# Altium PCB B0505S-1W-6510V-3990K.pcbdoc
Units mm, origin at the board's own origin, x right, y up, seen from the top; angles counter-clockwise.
Board outline 11.8 x 10.32 mm, 2 copper layers (Top Layer, Bottom Layer), stack 0.78 mm thick; 9 components, 9 nets, 28 pads, 12 vias.
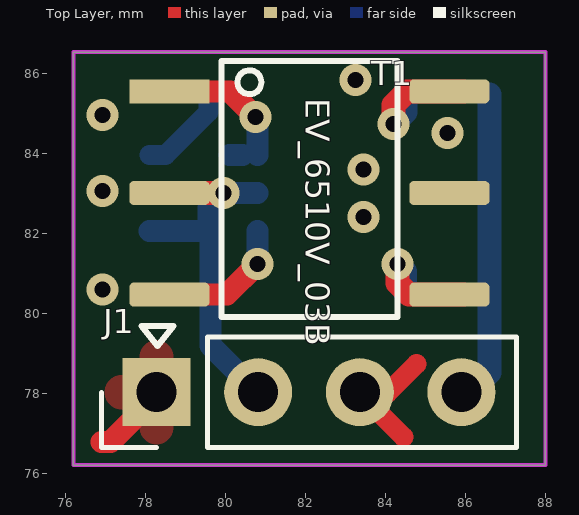
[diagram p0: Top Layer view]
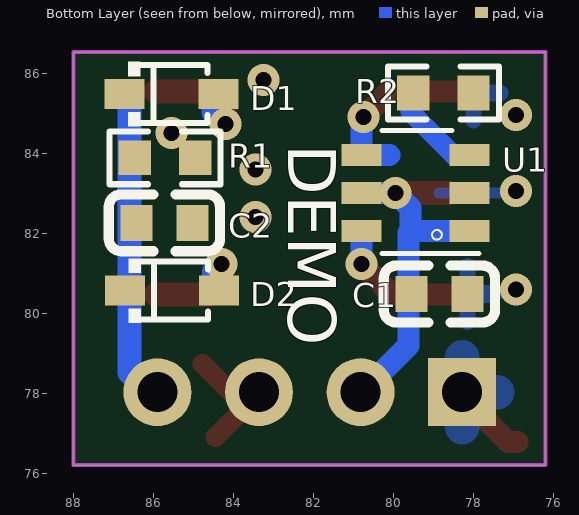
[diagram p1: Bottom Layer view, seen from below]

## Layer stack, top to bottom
Top Solder Mask Layer: solder mask 0.01, Dk 3.3
Top Layer: signal copper 0.035
Dielectric1: surface 0.71, FR4, Dk 4.5
Bottom Layer: signal copper 0.035
Bottom Solder Mask Layer: solder mask 0.01, Dk 3.3

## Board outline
76.2,86.52 88,86.52 88,76.2 76.2,76.2

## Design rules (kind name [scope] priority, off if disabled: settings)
BoardOutlineClearance safeClearance [All] p0: genericclearance=0.254 ignorepadtopadclearanceinfootprint=FALSE except(0: Arc-SplitContinuation Track-SplitContinuation SMDPad-SplitContinuation THPad-SplitContinuation Via-SplitContinuation Fill-SplitContinuation Poly-SplitContinuation Region-SplitContinuation Text-SplitContinuation)
BoardOutlineClearance Plane_innerPlane [All] p0: genericclearance=0.254 ignorepadtopadclearanceinfootprint=FALSE except(0: Arc-SplitContinuation Track-SplitContinuation SMDPad-SplitContinuation THPad-SplitContinuation Via-SplitContinuation Fill-SplitContinuation Poly-SplitContinuation Region-SplitContinuation Text-SplitContinuation)
BoardOutlineClearance Copper_CopperRegion [All] p0: genericclearance=0.254 ignorepadtopadclearanceinfootprint=FALSE except(0: Arc-SplitContinuation Track-SplitContinuation SMDPad-SplitContinuation THPad-SplitContinuation Via-SplitContinuation Fill-SplitContinuation Poly-SplitContinuation Region-SplitContinuation Text-SplitContinuation)
BoardOutlineClearance Copper_CopperRegion1 [All] p0: genericclearance=0.254 ignorepadtopadclearanceinfootprint=FALSE except(0: Arc-SplitContinuation Track-SplitContinuation SMDPad-SplitContinuation THPad-SplitContinuation Via-SplitContinuation Fill-SplitContinuation Poly-SplitContinuation Region-SplitContinuation Text-SplitContinuation)
BoardOutlineClearance Copper_CopperRegion2 [All] p0: genericclearance=0.254 ignorepadtopadclearanceinfootprint=FALSE except(0: Arc-SplitContinuation Track-SplitContinuation SMDPad-SplitContinuation THPad-SplitContinuation Via-SplitContinuation Fill-SplitContinuation Poly-SplitContinuation Region-SplitContinuation Text-SplitContinuation)
BoardOutlineClearance Copper_CopperRegion3 [All] p0: genericclearance=0.254 ignorepadtopadclearanceinfootprint=FALSE except(0: Arc-SplitContinuation Track-SplitContinuation SMDPad-SplitContinuation THPad-SplitContinuation Via-SplitContinuation Fill-SplitContinuation Poly-SplitContinuation Region-SplitContinuation Text-SplitContinuation)
BoardOutlineClearance otherClearance [All] p0: genericclearance=0.254 ignorepadtopadclearanceinfootprint=FALSE except(0: Arc-SplitContinuation Track-SplitContinuation SMDPad-SplitContinuation THPad-SplitContinuation Via-SplitContinuation Fill-SplitContinuation Poly-SplitContinuation Region-SplitContinuation Text-SplitContinuation)
Clearance safeClearance [All] p1: gap=0.178 ignorepadtopadclearanceinfootprint=FALSE
Clearance Plane_innerPlane [All] p1: gap=0.178 ignorepadtopadclearanceinfootprint=FALSE
Clearance Copper_CopperRegion [All] p1: gap=0.178 ignorepadtopadclearanceinfootprint=FALSE
Clearance Copper_CopperRegion1 [All] p1: gap=0.178 ignorepadtopadclearanceinfootprint=FALSE
Clearance Copper_CopperRegion2 [All] p1: gap=0.178 ignorepadtopadclearanceinfootprint=FALSE
Clearance Copper_CopperRegion3 [All] p1: gap=0.178 ignorepadtopadclearanceinfootprint=FALSE
Clearance otherClearance [All] p1: gap=0.178 ignorepadtopadclearanceinfootprint=FALSE
DiffPairsRouting differentialPair [All] p1: maxuncoupledlength=10 minlimit=6 maxlimit=Infinity mostfreqgap=6 toplayer_minwidth=5 toplayer_prefwidth=10 toplayer_maxwidth=100 bottomlayer_minwidth=5 bottomlayer_prefwidth=10 bottomlayer_maxwidth=100
PasteMaskExpansion Common [All] p1: expansion=0
PlaneConnect innerPlane [All] p1: planeconnectstyle=Relief reliefexpansion=0.508 reliefentries=4 reliefconductorwidth=0.254 reliefairgap=0.254
PolygonConnect CopperRegion [All] p1: connectstyle=Relief reliefentries=4 reliefconductorwidth=0 polygonreliefangle="90 Angle" airgapwidth=1
PolygonConnect CopperRegion1 [All] p1: connectstyle=Relief reliefentries=4 reliefconductorwidth=19.685 polygonreliefangle="90 Angle" airgapwidth=19.685
PolygonConnect CopperRegion2 [All] p1: connectstyle=Direct reliefentries=4 reliefconductorwidth=10 polygonreliefangle="90 Angle" airgapwidth=10
PolygonConnect CopperRegion3 [All] p1: connectstyle=Relief reliefentries=4 reliefconductorwidth=0 polygonreliefangle="90 Angle" airgapwidth=1
RoutingVias viaSize [All] p1: viastyle="Through Hole" holewidth=12 minholewidth=11.8 maxholewidth=236.2 width=12 minwidth=11.8 maxwidth=236.2
SolderMaskExpansion Common [All] p1: useseparateexpansions=TRUE expansion=0 expansionbottom=0
Width trackWidth [All] p1: maxlimit=100 minlimit=5 preferedwidth=10

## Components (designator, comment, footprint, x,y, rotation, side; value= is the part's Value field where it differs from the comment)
C1 "" C0603 78.85,80.475 r0 bottom
C2 "" C0603 85.725,82.254 r0 bottom
D1 "" SOD-323_L1.8-W1.3-LS2.5-RD 85.55,85.474 r180 bottom
D2 "" SOD-323_L1.8-W1.3-LS2.5-RD 85.538,80.56 r180 bottom
J1 "Connector_Generic_Conn_01x04" coileasy:PinHeader_01x04_P2.54mm_Vertical 78.27,78 r90 top
R1 "" R0603 85.71,83.88 r180 bottom
R2 "" R0603 78.75,85.5 r180 bottom
T1 "CMT3990K" coileasy:CMT38xxx 82.1,83 r0 top
U1 "" SOT-23-6_L2.9-W1.6-P0.95-LS2.8-BR 79.292,82.971 r0 bottom

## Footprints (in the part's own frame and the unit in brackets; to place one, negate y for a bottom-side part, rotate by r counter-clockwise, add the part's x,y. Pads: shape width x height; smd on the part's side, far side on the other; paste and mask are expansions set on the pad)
C0603 [mm]
  rect 0.8x0.9 smd: 1(-0.7,0) 2(0.7,0)
  silkscreen extent -1.39,-0.71 1.39,0.71
coileasy:CMT38xxx [mm]
  rect 2x0.6 smd: 1(-3.5,2.54)
  rrect37% 2x0.6 smd: 2(-3.5,0) 3(-3.5,-2.54) 4(3.5,-2.54) 5(3.5,0) 6(3.5,2.54)
  silkscreen extent -2.2,-3.1 2.2,3.3
coileasy:PinHeader_01x04_P2.54mm_Vertical [mm]
  rect 1.7x1.7 hole 1: 1(0.02,-0.01)
  round 1.7 hole 1: 2(0.02,-2.55) 3(0.02,-5.09) 4(0.02,-7.63)
  silkscreen extent -1.36,-9.01 1.4,1.37
R0603 [mm]
  rect 0.806x0.864 smd: 1(-0.753,0) 2(0.753,0)
  silkscreen extent -1.39,-0.66 1.39,0.66
SOD-323_L1.8-W1.3-LS2.5-RD [mm]
  rect 1x0.75 smd: 1(-1.173,0) 2(1.173,0)
  silkscreen extent -1.08,-0.8 0.9,0.8
SOT-23-6_L2.9-W1.6-P0.95-LS2.8-BR [mm]
  rect 1x0.55 smd: 1(-1.192,0.921) 2(-1.192,-0.029) 3(-1.192,-0.979) 4(1.508,-0.979) 5(1.508,-0.029) 6(1.508,0.921)
  silkscreen extent -1.43,-1.59 1,1.48

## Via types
v1: diameter 0.8, hole 0.4, Top Layer to Bottom Layer, 12 vias

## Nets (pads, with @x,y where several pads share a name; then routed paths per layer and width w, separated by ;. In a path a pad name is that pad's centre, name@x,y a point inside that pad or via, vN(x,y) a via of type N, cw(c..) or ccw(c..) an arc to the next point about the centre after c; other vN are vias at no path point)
0V: C2.1 J1.3 R1.2 T1.5 | length 3.3
  Top Layer w0.5: 84.45,76.9 83.35,78 84.05,78 84.775,78.725
  other v1: 83.45,82.4 83.45,83.585 85.55,84.5 83.253,85.82
$1N9: D1.2 T1.6 | length 3.2
  Top Layer w0.6: v1(84.2,84.725) 84.2,85.2 84.54,85.54 T1.6@85.95,85.54
  Bottom Layer w0.6: v1(84.2,84.725) 84.5,85.025 D1.2@84.5,85.464
$1N11: D2.2 T1.4 | length 3
  Top Layer w0.6: v1(84.3,81.225) 84.3,80.75 84.59,80.46 T1.4@85.95,80.46
  Bottom Layer w0.6: v1(84.3,81.225) 84.488,81.037 D2.2@84.488,80.515
+VO: C2.2 D1.1 D2.1 J1.4 R1.1 | length 7.9
  Bottom Layer w0.6: J1.4@85.89,78 86.09,78 86.6,78.51 D1.1@86.6,85.464
CLK: R2.1 U1.3 | length 2.4
  Bottom Layer w0.5: U1.3 78.5,83.95 79.575,85.025 R2.1@79.575,85.5
GND: C1.1 J1.1 R2.2 U1.2 | length 2
  Top Layer w0.55: 76.9,76.776 77.126,76.776 78.27,77.92 J1.1@78.27,78
  Bottom Layer w0.55: J1.1@78.15,78 J1.1@78.27,78
  other v1: 76.932,80.583 76.932,83.049 76.932,84.95
VD1: T1.3 U1.6 | length 3.7
  Top Layer w0.55: T1.3@78.25,80.46 80.035,80.46 v1(80.8,81.225)
  Bottom Layer w0.55: v1(80.8,81.225) U1.6
VD2: T1.1 U1.4 | length 4.4
  Top Layer w0.55: T1.1@77.9,85.54 80.11,85.54 v1(80.75,84.9)
  Bottom Layer w0.55: 80.1,83.95 U1.4@80.425,83.95 ; v1(80.75,84.9) 80.8,84.85 U1.4
VIN: C1.2 J1.2 T1.2 U1.1 U1.5 | length 10.3
  Top Layer w0.6: T1.2 v1(79.95,83)
  Bottom Layer w0.55: U1.1 79.575,82.05 ; U1.5 v1(79.95,83) 79.575,82.625 79.575,82.05 ; J1.2@80.81,78.365 J1.2@80.81,78 ; J1.2@81.076,78.066 80.81,77.8 J1.2@80.81,78 ; 79.575,82.05 79.625,82 79.625,79.185 J1.2@80.81,78

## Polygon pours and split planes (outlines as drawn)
0V on Top Layer (solid, remove dead copper, pour order 0): 88,76.2 88,86.5 82.8,86.5 82.8,76.2
0V on Bottom Layer (solid, remove dead copper, pour order 4): 88,76.2 88,86.5 82.8,86.5 82.8,76.2
GND on Top Layer (solid, remove dead copper, pour order 2): 76.2,76.2 76.2,86.5 79.05,86.5 79.05,76.2
GND on Bottom Layer (solid, remove dead copper, pour order 6): 76.2,76.2 76.2,86.5 79.05,86.5 79.05,76.2

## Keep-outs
Board Outline Layer:
  the board outline again, w0.1

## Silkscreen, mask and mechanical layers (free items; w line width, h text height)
Top Silkscreen Layer:
  lines w0.15: 77.9,79.676 78.7,79.676 78.3,79.176 77.9,79.676
  text "EV_6510V_03B" at 82.004,85.373 h0.6 r270
Bottom Silkscreen Layer:
  text "DEMO" at 82.623,84.223 h1.2 r90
